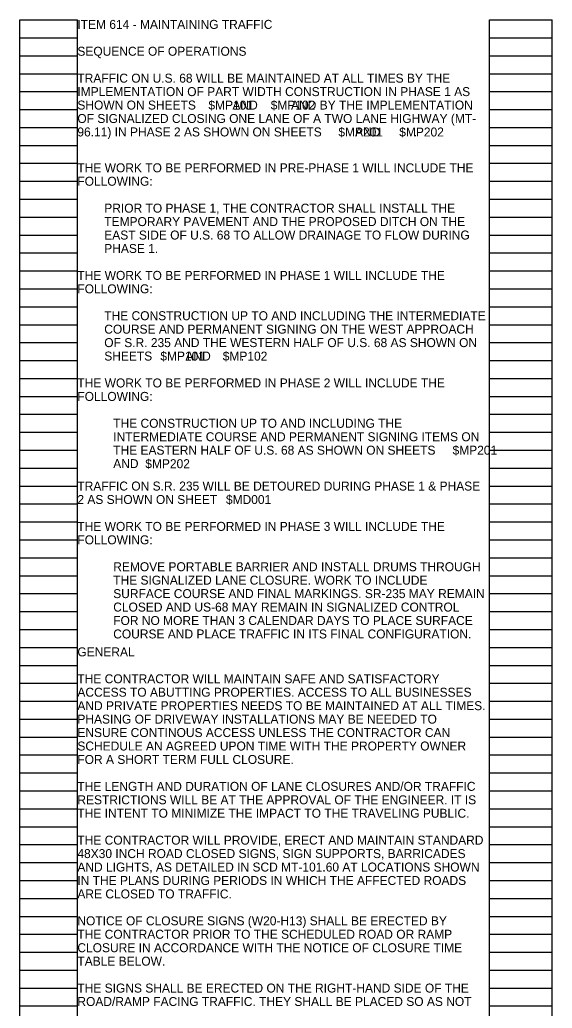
# Model space of a CAD drawing. Extents: x 11124 to 11156, y 1608 to 1730.
# Drawn here: x 11125.9 to 11134.22, y 1714.77 to 1730.21 of the extents above; entities that cross this region are included whole.
import ezdxf

# ---------------------------------------------------------------- set-up
doc = ezdxf.new("R2010")
doc.units = 0
doc.layers.add('SC_Scratch1', color=7, linetype='Continuous')
doc.layers.add('SH_Text', color=7, linetype='Continuous')

msp = doc.modelspace()

# ---------------------------------------------------------------- linework, layer by layer
at = {"layer": 'SC_Scratch1'}
for p, q in [((11125.896, 1710.049), (11125.896, 1730.209)), ((11125.896, 1730.209), (11126.796, 1730.209)), ((11126.796, 1710.049), (11126.796, 1730.209)), ((11133.236, 1710.049), (11133.236, 1730.209)), ((11133.236, 1730.209), (11134.216, 1730.209)), ((11134.216, 1710.049), (11134.216, 1730.209)), ((11125.896, 1729.929), (11126.796, 1729.929)), ((11133.236, 1729.929), (11134.216, 1729.929)), ((11125.896, 1729.649), (11126.796, 1729.649)), ((11133.236, 1729.649), (11134.216, 1729.649)), ((11125.896, 1729.369), (11126.796, 1729.369)), ((11133.236, 1729.369), (11134.216, 1729.369)), ((11125.896, 1729.089), (11126.796, 1729.089)), ((11133.236, 1729.089), (11134.216, 1729.089)), ((11125.896, 1728.809), (11126.796, 1728.809)), ((11133.236, 1728.809), (11134.216, 1728.809)), ((11125.896, 1728.529), (11126.796, 1728.529)), ((11133.236, 1728.529), (11134.216, 1728.529)), ((11125.896, 1728.249), (11126.796, 1728.249)), ((11133.236, 1728.249), (11134.216, 1728.249)), ((11125.896, 1727.969), (11126.796, 1727.969)), ((11133.236, 1727.969), (11134.216, 1727.969)), ((11125.896, 1727.689), (11126.796, 1727.689)), ((11133.236, 1727.689), (11134.216, 1727.689)), ((11125.896, 1727.409), (11126.796, 1727.409)), ((11133.236, 1727.409), (11134.216, 1727.409)), ((11125.896, 1727.129), (11126.796, 1727.129)), ((11133.236, 1727.129), (11134.216, 1727.129)), ((11125.896, 1726.849), (11126.796, 1726.849)), ((11133.236, 1726.849), (11134.216, 1726.849)), ((11125.896, 1726.569), (11126.796, 1726.569)), ((11133.236, 1726.569), (11134.216, 1726.569)), ((11125.896, 1726.289), (11126.796, 1726.289)), ((11133.236, 1726.289), (11134.216, 1726.289)), ((11125.896, 1726.009), (11126.796, 1726.009)), ((11133.236, 1726.009), (11134.216, 1726.009)), ((11125.896, 1725.729), (11126.796, 1725.729)), ((11133.236, 1725.729), (11134.216, 1725.729)), ((11125.896, 1725.449), (11126.796, 1725.449)), ((11133.236, 1725.449), (11134.216, 1725.449)), ((11125.896, 1725.169), (11126.796, 1725.169)), ((11133.236, 1725.169), (11134.216, 1725.169)), ((11125.896, 1724.889), (11126.796, 1724.889)), ((11133.236, 1724.889), (11134.216, 1724.889)), ((11125.896, 1724.609), (11126.796, 1724.609)), ((11133.236, 1724.609), (11134.216, 1724.609)), ((11125.896, 1724.329), (11126.796, 1724.329)), ((11133.236, 1724.329), (11134.216, 1724.329)), ((11125.896, 1724.049), (11126.796, 1724.049)), ((11133.236, 1724.049), (11134.216, 1724.049)), ((11125.896, 1723.769), (11126.796, 1723.769)), ((11133.236, 1723.769), (11134.216, 1723.769)), ((11125.896, 1723.489), (11126.796, 1723.489)), ((11133.236, 1723.489), (11134.216, 1723.489)), ((11125.896, 1723.209), (11126.796, 1723.209)), ((11133.236, 1723.209), (11134.216, 1723.209)), ((11125.896, 1722.929), (11126.796, 1722.929)), ((11133.236, 1722.929), (11134.216, 1722.929)), ((11125.896, 1722.649), (11126.796, 1722.649)), ((11133.236, 1722.649), (11134.216, 1722.649)), ((11125.896, 1722.369), (11126.796, 1722.369)), ((11133.236, 1722.369), (11134.216, 1722.369)), ((11125.896, 1722.089), (11126.796, 1722.089)), ((11133.236, 1722.089), (11134.216, 1722.089)), ((11125.896, 1721.809), (11126.796, 1721.809)), ((11133.236, 1721.809), (11134.216, 1721.809)), ((11125.896, 1721.529), (11126.796, 1721.529)), ((11133.236, 1721.529), (11134.216, 1721.529)), ((11125.896, 1721.249), (11126.796, 1721.249)), ((11133.236, 1721.249), (11134.216, 1721.249)), ((11125.896, 1720.969), (11126.796, 1720.969)), ((11133.236, 1720.969), (11134.216, 1720.969)), ((11125.896, 1720.689), (11126.796, 1720.689)), ((11133.236, 1720.689), (11134.216, 1720.689)), ((11125.896, 1720.409), (11126.796, 1720.409)), ((11133.236, 1720.409), (11134.216, 1720.409)), ((11125.896, 1720.129), (11126.796, 1720.129)), ((11133.236, 1720.129), (11134.216, 1720.129)), ((11125.896, 1719.849), (11126.796, 1719.849)), ((11133.236, 1719.849), (11134.216, 1719.849)), ((11125.896, 1719.569), (11126.796, 1719.569)), ((11133.236, 1719.569), (11134.216, 1719.569)), ((11125.896, 1719.289), (11126.796, 1719.289)), ((11133.236, 1719.289), (11134.216, 1719.289)), ((11125.896, 1719.009), (11126.796, 1719.009)), ((11133.236, 1719.009), (11134.216, 1719.009)), ((11125.896, 1718.729), (11126.796, 1718.729)), ((11133.236, 1718.729), (11134.216, 1718.729)), ((11125.896, 1718.449), (11126.796, 1718.449)), ((11133.236, 1718.449), (11134.216, 1718.449)), ((11125.896, 1718.169), (11126.796, 1718.169)), ((11133.236, 1718.169), (11134.216, 1718.169)), ((11125.896, 1717.889), (11126.796, 1717.889)), ((11133.236, 1717.889), (11134.216, 1717.889)), ((11125.896, 1717.609), (11126.796, 1717.609)), ((11133.236, 1717.609), (11134.216, 1717.609)), ((11125.896, 1717.329), (11126.796, 1717.329)), ((11133.236, 1717.329), (11134.216, 1717.329)), ((11125.896, 1717.049), (11126.796, 1717.049)), ((11133.236, 1717.049), (11134.216, 1717.049)), ((11125.896, 1716.769), (11126.796, 1716.769)), ((11133.236, 1716.769), (11134.216, 1716.769)), ((11125.896, 1716.489), (11126.796, 1716.489)), ((11133.236, 1716.489), (11134.216, 1716.489)), ((11125.896, 1716.209), (11126.796, 1716.209)), ((11133.236, 1716.209), (11134.216, 1716.209)), ((11125.896, 1715.929), (11126.796, 1715.929)), ((11133.236, 1715.929), (11134.216, 1715.929)), ((11125.896, 1715.649), (11126.796, 1715.649)), ((11133.236, 1715.649), (11134.216, 1715.649)), ((11125.896, 1715.369), (11126.796, 1715.369)), ((11133.236, 1715.369), (11134.216, 1715.369)), ((11125.896, 1715.089), (11126.796, 1715.089)), ((11133.236, 1715.089), (11134.216, 1715.089)), ((11125.896, 1714.809), (11126.796, 1714.809)), ((11133.236, 1714.809), (11134.216, 1714.809))]:
    msp.add_line(p, q, dxfattribs=at)

# ---------------------------------------------------------------- texts
at = {"layer": 'SH_Text'}
for s, p in [('ITEM 614 - MAINTAINING TRAFFIC', (11126.796, 1730.069)), ('SEQUENCE OF OPERATIONS', (11126.796, 1729.649)), ('TRAFFIC ON U.S. 68 WILL BE MAINTAINED AT ALL TIMES BY THE ', (11126.796, 1729.229)), ('IMPLEMENTATION OF PART WIDTH CONSTRUCTION IN PHASE 1 AS ', (11126.796, 1729.019)), ('SHOWN ON SHEETS           AND          AND BY THE IMPLEMENTATION ', (11126.796, 1728.809)), ('$MP101', (11128.843, 1728.808)), ('$MP102', (11129.817, 1728.808)), ('OF SIGNALIZED CLOSING ONE LANE OF A TWO LANE HIGHWAY (MT-', (11126.796, 1728.599)), ('96.11) IN PHASE 2 AS SHOWN ON SHEETS          AND          .', (11126.796, 1728.389)), ('$MP201', (11130.874, 1728.388)), ('$MP202', (11131.825, 1728.388)), ('THE WORK TO BE PERFORMED IN PRE-PHASE 1 WILL INCLUDE THE ', (11126.796, 1727.829)), ('FOLLOWING:', (11126.796, 1727.619)), ('PRIOR TO PHASE 1, THE CONTRACTOR SHALL INSTALL THE ', (11127.216, 1727.199)), ('TEMPORARY PAVEMENT AND THE PROPOSED DITCH ON THE ', (11127.216, 1726.989)), ('EAST SIDE OF U.S. 68 TO ALLOW DRAINAGE TO FLOW DURING ', (11127.216, 1726.779)), ('PHASE 1.', (11127.216, 1726.569)), ('THE WORK TO BE PERFORMED IN PHASE 1 WILL INCLUDE THE ', (11126.796, 1726.149)), ('FOLLOWING:', (11126.796, 1725.939)), ('THE CONSTRUCTION UP TO AND INCLUDING THE INTERMEDIATE ', (11127.216, 1725.519)), ('COURSE AND PERMANENT SIGNING ON THE WEST APPROACH ', (11127.216, 1725.309)), ('OF S.R. 235 AND THE WESTERN HALF OF U.S. 68 AS SHOWN ON ', (11127.216, 1725.099)), ('SHEETS          AND         . ', (11127.216, 1724.889)), ('$MP101', (11128.092, 1724.888)), ('$MP102', (11129.067, 1724.888)), ('THE WORK TO BE PERFORMED IN PHASE 2 WILL INCLUDE THE ', (11126.796, 1724.469)), ('FOLLOWING:', (11126.796, 1724.259)), ('THE CONSTRUCTION UP TO AND INCLUDING THE ', (11127.356, 1723.839)), ('INTERMEDIATE COURSE AND PERMANENT SIGNING ITEMS ON ', (11127.356, 1723.629)), ('THE EASTERN HALF OF U.S. 68 AS SHOWN ON SHEETS          ', (11127.356, 1723.419)), ('$MP201', (11132.658, 1723.419)), ('AND      ', (11127.356, 1723.209)), ('$MP202', (11127.857, 1723.208)), ('TRAFFIC ON S.R. 235 WILL BE DETOURED DURING PHASE 1 & PHASE ', (11126.796, 1722.859)), ('2 AS SHOWN ON SHEET        .', (11126.796, 1722.649)), ('$MD001', (11129.117, 1722.648)), ('THE WORK TO BE PERFORMED IN PHASE 3 WILL INCLUDE THE ', (11126.796, 1722.229)), ('FOLLOWING:', (11126.796, 1722.019)), ('REMOVE PORTABLE BARRIER AND INSTALL DRUMS THROUGH ', (11127.356, 1721.599)), ('THE SIGNALIZED LANE CLOSURE. WORK TO INCLUDE ', (11127.356, 1721.389)), ('SURFACE COURSE AND FINAL MARKINGS. SR-235 MAY REMAIN ', (11127.356, 1721.179)), ('CLOSED AND US-68 MAY REMAIN IN SIGNALIZED CONTROL ', (11127.356, 1720.969)), ('FOR NO MORE THAN 3 CALENDAR DAYS TO PLACE SURFACE ', (11127.356, 1720.759)), ('COURSE AND PLACE TRAFFIC IN ITS FINAL CONFIGURATION.', (11127.356, 1720.549)), ('GENERAL', (11126.796, 1720.269)), ('THE CONTRACTOR WILL MAINTAIN SAFE AND SATISFACTORY ', (11126.796, 1719.849)), ('ACCESS TO ABUTTING PROPERTIES. ACCESS TO ALL BUSINESSES ', (11126.796, 1719.639)), ('AND PRIVATE PROPERTIES NEEDS TO BE MAINTAINED AT ALL TIMES. ', (11126.796, 1719.429)), ('PHASING OF DRIVEWAY INSTALLATIONS MAY BE NEEDED TO ', (11126.796, 1719.219)), ('ENSURE CONTINOUS ACCESS UNLESS THE CONTRACTOR CAN ', (11126.796, 1719.009)), ('SCHEDULE AN AGREED UPON TIME WITH THE PROPERTY OWNER ', (11126.796, 1718.799)), ('FOR A SHORT TERM FULL CLOSURE.', (11126.796, 1718.589)), ('THE LENGTH AND DURATION OF LANE CLOSURES AND/OR TRAFFIC ', (11126.796, 1718.169)), ('RESTRICTIONS WILL BE AT THE APPROVAL OF THE ENGINEER. IT IS ', (11126.796, 1717.959)), ('THE INTENT TO MINIMIZE THE IMPACT TO THE TRAVELING PUBLIC.', (11126.796, 1717.749)), ('THE CONTRACTOR WILL PROVIDE, ERECT AND MAINTAIN STANDARD ', (11126.796, 1717.329)), ('48X30 INCH ROAD CLOSED SIGNS, SIGN SUPPORTS, BARRICADES ', (11126.796, 1717.119)), ('AND LIGHTS, AS DETAILED IN SCD MT-101.60 AT LOCATIONS SHOWN ', (11126.796, 1716.909)), ('IN THE PLANS DURING PERIODS IN WHICH THE AFFECTED ROADS ', (11126.796, 1716.699)), ('ARE CLOSED TO TRAFFIC.', (11126.796, 1716.489)), ('NOTICE OF CLOSURE SIGNS (W20-H13) SHALL BE ERECTED BY ', (11126.796, 1716.069)), ('THE CONTRACTOR PRIOR TO THE SCHEDULED ROAD OR RAMP ', (11126.796, 1715.859)), ('CLOSURE IN ACCORDANCE WITH THE NOTICE OF CLOSURE TIME ', (11126.796, 1715.649)), ('TABLE BELOW. ', (11126.796, 1715.439)), ('THE SIGNS SHALL BE ERECTED ON THE RIGHT-HAND SIDE OF THE ', (11126.796, 1715.019)), ('ROAD/RAMP FACING TRAFFIC. THEY SHALL BE PLACED SO AS NOT ', (11126.796, 1714.809))]:
    msp.add_text(s, height=0.14, dxfattribs=at).set_placement(p)

doc.saveas('drawing.dxf')
